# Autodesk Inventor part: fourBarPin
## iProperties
Created: 2008-10
Part Number: fourBarPin
Document SubType Name: Modeling
Designer: Lochan
Density: 1 g/cm^3
Mass: 1.34688 g
Surface Area: 12.4893 cm^2
Volume: 1.34688 cm^3
Author: Lochan
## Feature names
1. Extrusion1
2. Extrusion2
